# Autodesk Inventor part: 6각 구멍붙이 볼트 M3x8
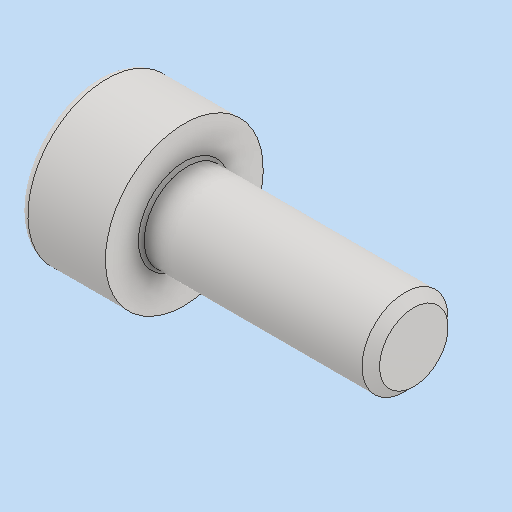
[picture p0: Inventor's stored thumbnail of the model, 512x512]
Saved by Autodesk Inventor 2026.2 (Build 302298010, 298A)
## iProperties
Created: 2026-08
Part Number: 6각 구멍붙이 볼트 M3x8
Material: 스테인리스강
Description: 6각 소켓 머리 캡 나사
Document SubType Name: Modeling
Designer: PC2-02
Density: 8.08 g/cm^3
Appearance: 기본값
Author: jhkim
Sending System: Autodesk Inventor 2027
Preprocessor: ST-DEVELOPER v20.1
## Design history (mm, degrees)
feature "Solid1"
node "솔리드1"
